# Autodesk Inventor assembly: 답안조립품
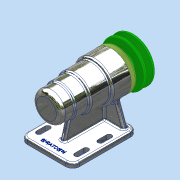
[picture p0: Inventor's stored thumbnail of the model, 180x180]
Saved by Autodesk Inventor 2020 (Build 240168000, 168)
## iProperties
Created: 2021-10
Part Number: 답안조립품
Document SubType Name: Assembly
Designer: user
Author: user
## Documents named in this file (12)
- C:\Users\user\Desktop\711007V1014\답안조립품.iam
- C:\Users\user\Desktop\711007V1014\V벨트풀리.ipt
- C:\Users\user\Desktop\711007V1014\멈춤나사 M3.ipt
- C:\Users\user\Desktop\711007V1014\베어링 6004.ipt
- C:\Users\user\Desktop\711007V1014\베어링 51202.ipt
- C:\Users\user\Desktop\711007V1014\본체.ipt
- C:\Users\user\Desktop\711007V1014\볼트 M4.ipt
- C:\Users\user\Desktop\711007V1014\어댑터슬리브.ipt
- C:\Users\user\Desktop\711007V1014\오일 실 20x35x7.ipt
- C:\Users\user\Desktop\711007V1014\축.ipt
- C:\Users\user\Desktop\711007V1014\커버.ipt
- C:\Users\user\Desktop\711007V1014\키 5x5.ipt
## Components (1 placed, 1 different names)
1. V벨트풀리:1
